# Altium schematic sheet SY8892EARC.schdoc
size 127 x 101 mm
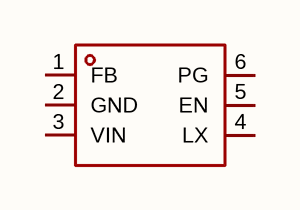
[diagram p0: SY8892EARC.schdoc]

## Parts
U?  sy8892earc  [SOT-563-6_L1.6-W1.2-P0.50-LS1.6-TL]  (value not drawn)

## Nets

Not connected (* = marked no-connect by the designer): U? 1(FB) 2(GND) 3(VIN) 4(LX) 5(EN) 6(PG)

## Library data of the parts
U? = sy8892earc: 功能类型:降压型;工作电压:2.5V~5.5V;输出电压:-;输出电流:2A;输出类型:可调;; Manufacturer: Silergy(矽力杰); AddInBom: yes; ModelId: 93b39b52aa3347c1963e51aa7f5c0a5e; ModelTransform: 62.992,62.992,0,0,0,0,0.007,0.006,0; Function: 降压型; Output Current: 2A; Frequency - Switching: 1.5MHz; Synchronous Rectifier: 是; Number of Outputs: 1; Topology: 降压式; Switch tube (built-in/external): 内置; Output Type: 可调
